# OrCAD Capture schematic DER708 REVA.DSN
size Custom
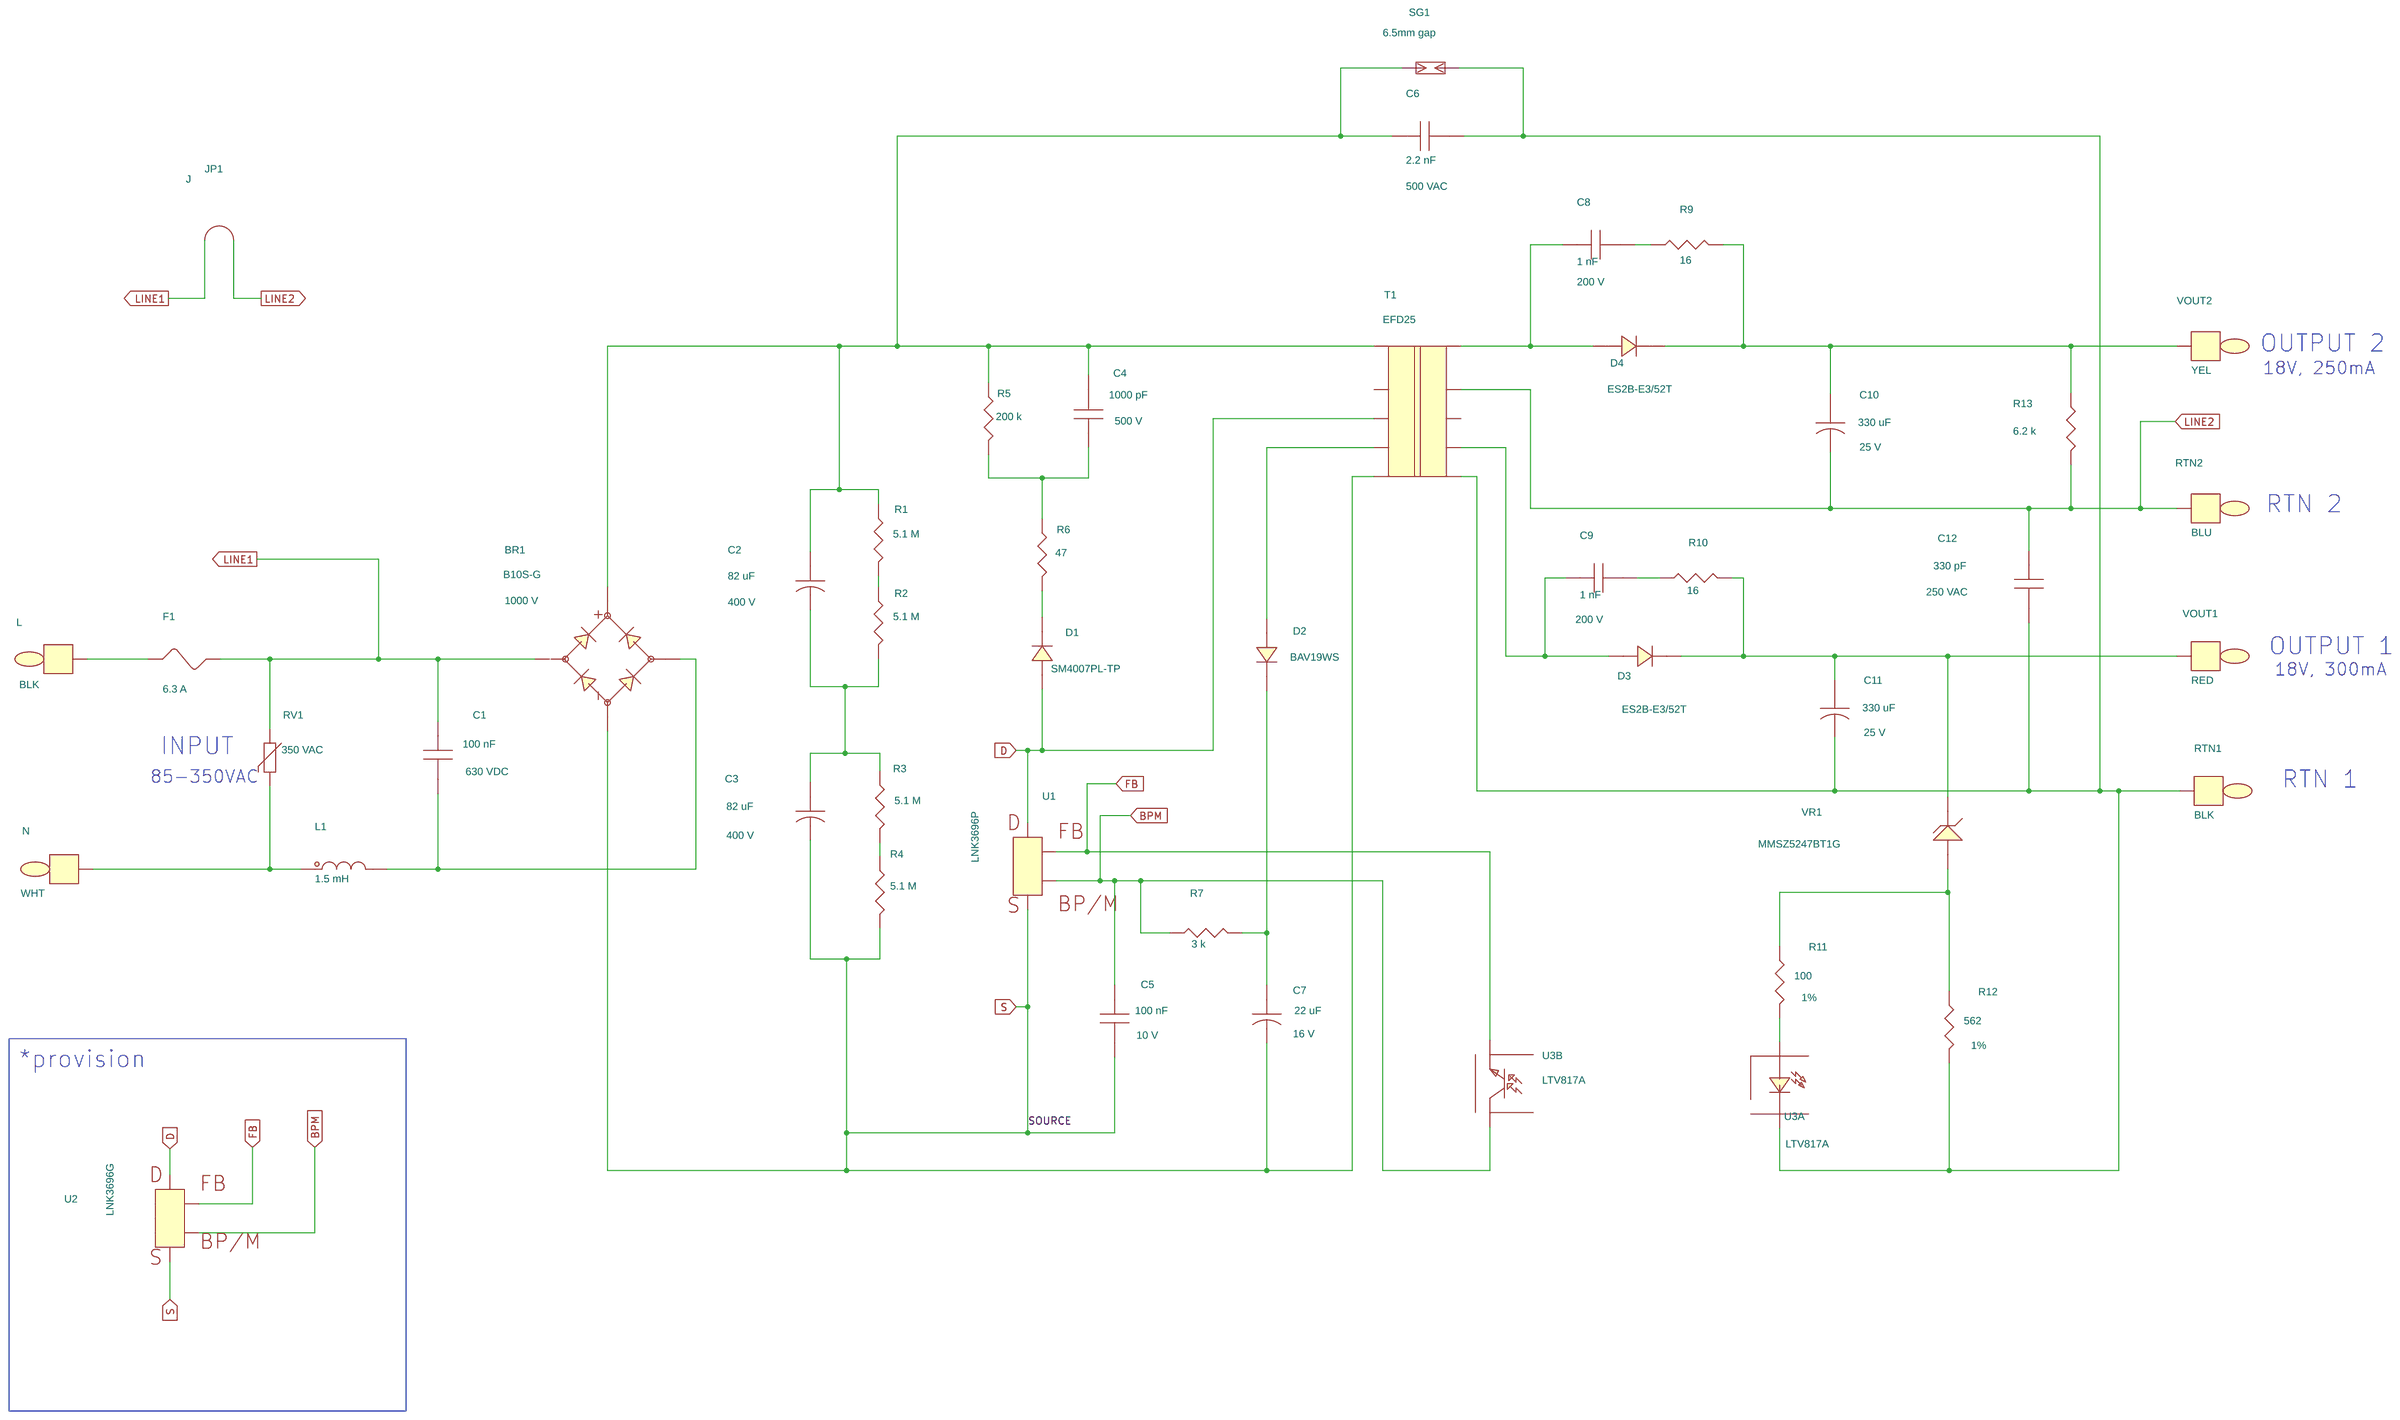
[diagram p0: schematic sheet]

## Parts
BR1  B10S-G  [pismsoic4]
C1  100 nF  [pi_np_cap12p5L6p0w10p0lsd040]
C2  82 uF  [pipolcapd16x25mmd40]
C3  82 uF  [pipolcapd16x25mmd40]
C4  1000 pF  [pismc0805]
C5  100 nF  [pismc0805]
C6  2.2 nF  [pinpycaprad540x290ls400040]
C7  22 uF  [pipolcapclyd200ls80030]
C8  1 nF  [pismc0805]
C9  1 nF  [pismc0805]
C10  330 uF  [pipolcapclyd320ls140030]
C11  330 uF  [pipolcapclyd320ls140030]
C12  330 pF  [pinpycaprad470x210ls380040]
D1  SM4007PL-TP  [pi_sm_sod-123_12]
D2  BAV19WS  [pismsod323]
D3  ES2B-E3/52T  [pismdo214aa12]
D4  ES2B-E3/52T  [pismdo214aa12]
F1  6.3 A  [PI_V_AX_BEL_0697H]
JP1  J  [pi_jumper400]
L  BLK  [pitpkeystone125x125]
L1  1.5 mH  [pi_choke_RLB9012_D2]
N  WHT  [pitpkeystone125x125]
R1  5.1 M  [pismr1206]
R2  5.1 M  [pismr1206]
R3  5.1 M  [pismr1206]
R4  5.1 M  [pismr1206]
R5  200 k  [pismr1206]
R6  47  [pismr1206]
R7  3 k  [pismr1206]
R9  16  [pismr0805]
R10  16  [pismr0805]
R11  100  [pismr0805]
R12  562  [pismr1206]
R13  6.2 k  [pismr0603]
RTN1  BLK  [pitpkeystone125x125]
RTN2  BLU  [pitpkeystone125x125]
RV1  350 VAC  [pi_radD10p5xT8p1xLS7p5d031]
SG1  6.5mm gap  [PI_SPARK_GAP_6p5MM]
T1  EFD25  [pi_bobbin_efd25_10p]
U1  LNK3696P  [piicdip8cshort5678]
U2  LNK3696G  [piicsmd8cshort5678]
U3  LTV817A  [pi_dip4]  (sections A,B)
VOUT1  RED  [pitpkeystone125x125]
VOUT2  YEL  [pitpkeystone125x125]
VR1  MMSZ5247BT1G  [pi_sm_sod-123_12]

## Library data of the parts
BR1 = DIODE_BRIDGE_~~+-: ALT_SYMBOLS: pi_sm_soic4_slot; Disp_Voltage: 1000 V; FPLIST: pismsoic4,pi_sm_soic4_slot; Part Number: 15-00818-00
C1 = CAP_NP: Disp_Voltage: 630 VDC; Part Number: 20-02095-00; Voltage: 630 VDC
C2 C3 = CAP_POL: ALT_SYMBOLS: pipolcapd16x25mmd40H; Disp_Voltage: 400 V; FPLIST: pipolcapd16x25mmd40,pipolcapd16x25mmd40H; Part Number: 20-01526-00; Voltage: 400 V
C4 = CAP_NP: Disp_Voltage: 500 V; Part Number: 20-09036-00; Voltage: 500 V
C5 = CAP_NP: Disp_Voltage: 10 V; Part Number: 20-01399-00; Voltage: 10 V
C6 = CAP_NP: ALT_SYMBOLS: pinpycaprad540x290ls400040h; Disp_Voltage: 500 VAC; FPLIST: pinpycaprad540x290ls400040,pinpycaprad540x290ls400040h; Part Number: 20-00376-00; Voltage: 250 VAC
C7 = CAP_POL: ALT_SYMBOLS: pipolcapclyd200ls80030h; Disp_Voltage: 16 V; FPLIST: pipolcapclyd200ls80030,pipolcapclyd200ls80030h; Part Number: 20-00678-00; Voltage: 16 V
C8 C9 = CAP_NP: ALT_SYMBOLS: pismc0805_1; Disp_Voltage: 200 V; FPLIST: pismc0805,pismc0805_1; Part Number: 20-00737-00; Voltage: 200 V
C10 C11 = CAP_POL: Disp_Voltage: 25 V; FPLIST: pipolcapclyd320ls140030,pipolcapclyd320ls140030430h; Part Number: 20-00029-00; Voltage: 25 V
C12 = CAP_NP: Disp_Voltage: 250 VAC; Part Number: 20-00373-00; Voltage: 250 VAC
D1 = DIODE: Part Number: 15-01070-00
D2 = DIODE: Part Number: 15-00658-00
D3 D4 = DIODE: Part Number: 15-00166-00
F1 = FUSE: ALT_SYMBOLS: PI_V_AX_BEL_0697H_H; FPLIST: PI_V_AX_BEL_0697H,PI_V_AX_BEL_0697H_H; Part Number: 40-00089-00
JP1 = JUMPER_1: Part Number: 65-00121-00
L RTN1 = TESTPOINT: Part Number: 35-00042-00
L1 = INDUCTOR_DOT2: Part Number: 30-00423-00
N = TESTPOINT: Part Number: 35-00044-00
R1-R4 = R: Part Number: 05-01438-00
R5 = R: Part Number: 05-01407-00
R6 = R: Part Number: 05-01320-00
R7 = R: Part Number: 05-01363-00
R9 R10 = R: COMPGROUP: 2; Part Number: 05-01476-00
R11 = R: Disp_Tol: 1%; Part Number: 05-00588-00
R12 = R: Disp_Tol: 1%; Part Number: 05-00169-00
R13 = R: Part Number: 05-01707-00
RTN2 = TESTPOINT: Part Number: 35-00185-00
RV1 = VARISTOR: ALT_SYMBOLS: pi_radD10p5xT8p1xLS7p5d031H; FPLIST: pi_radD10p5xT8p1xLS7p5d031,pi_radD10p5xT8p1xLS7p5d031H; Part Number: 85-00048-00
SG1 = SPARK_GAP: Part Number: 66-00355-00
T1 = BEFD25_1: Part Number: 25-00017-00
U1 = LNK3696_3: Part Number: 10-01089-00
U2 = LNK3696_4: FPLIST: piicsmd8cshort5678ipc,piicsmd8cshort5678; Part Number: 10-01088-00
U3 = OPTO_A_B: Part Number: 53-00008-00
VOUT1 = TESTPOINT: Part Number: 35-00043-00
VOUT2 = TESTPOINT: Part Number: 35-00046-00
VR1 = DIODE_ZENER: Part Number: 15-01362-00

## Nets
BPM: C5.1 R7.1 U1.1(BP/M) U2.1(BP/M) U3.4(C)
D: D1.2 T1.3 U1.4(D) U2.4(D)
FB: U1.2(FB) U2.2(FB) U3.3(E)
LINE1: BR1.2 C1.1 F1.2 JP1.1 RV1.1
LINE2: C10.2 C12.1 JP1.2 R13.2 RTN2.1 T1.10
S: BR1.4 C3.2 C5.2 C7.2 R4.2 T1.5 U1.5(S) U2.5(S)
N4274193: BR1.3 C2.1 C4.2 C6.1 R1.1 R5.2 SG1.1 T1.1
N4274205: C6.2 C11.2 C12.2 R12.2 RTN1.1 SG1.2 T1.7 U3.2(C)
N4274243: C8.1 D4.2 T1.9
N4274251: C8.2 R9.1
N4274255: C10.1 D4.1 R9.2 R13.1 VOUT2.1
N4274611: C9.1 D3.2 T1.6
N4274619: C11.1 D3.1 R10.2 VOUT1.1 VR1.1
N4274661: C4.1 R5.1 R6.1
N4274675: R1.2 R2.1
N4274879: F1.1 L.1
N4274899: C2.2 C3.1 R2.2 R3.1
N4275119: R11.1 R12.1 VR1.2
N4275169: R3.2 R4.1
N4275423: R11.2 U3.1(A)
N4275545: C7.1 D2.1 R7.2
N4276562: C9.2 R10.1
N4280018: BR1.1 C1.2 L1.1
N4280035: L1.2 N.1 RV1.2
N4320039: D2.2 T1.4
N4335305: D1.1 R6.2

Not connected (* = marked no-connect by the designer): T1 2 8; U1 6(S6) 7(S7) 8(S8); U2 6(S6) 7(S7) 8(S8)

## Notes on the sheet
- OUTPUT 2
- 18V, 250mA
- RTN 2
- OUTPUT 1
- 18V, 300mA
- INPUT
- 85-350VAC
- RTN 1
- *provision
